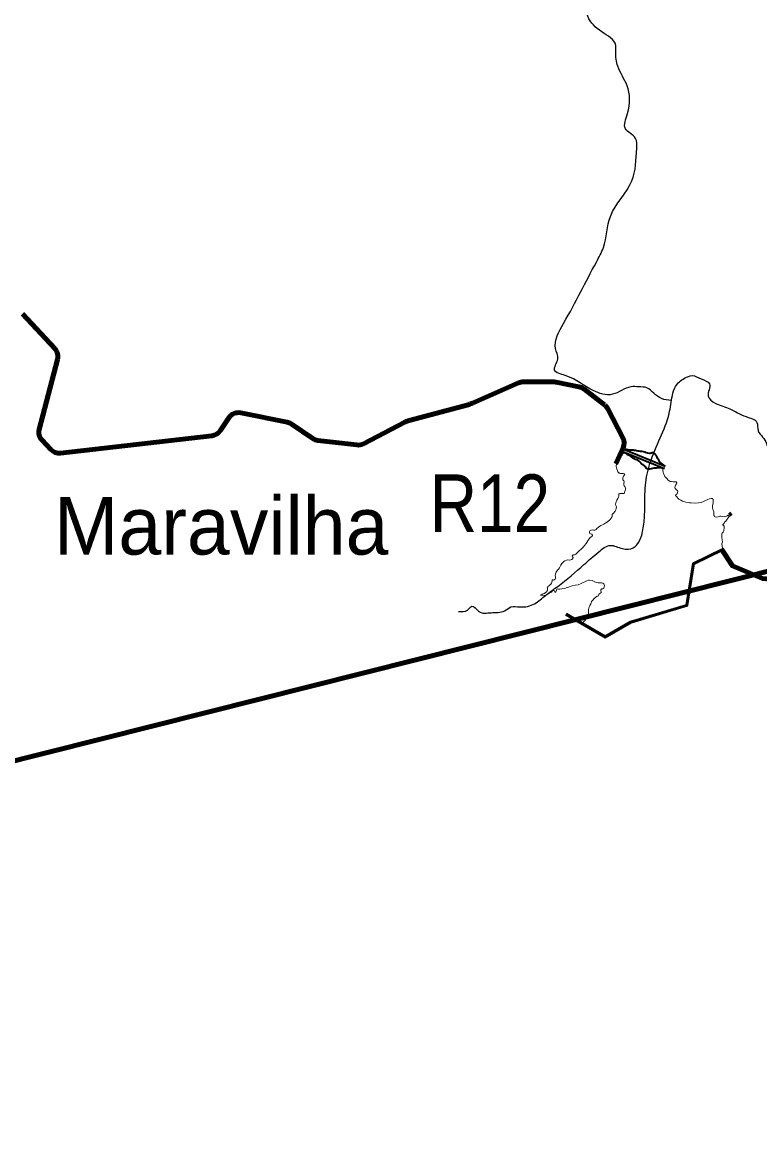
# Model space of a CAD drawing. Extents: x 553962 to 842807, y 8883888 to 9032388.
# Drawn here: x 681628 to 688018, y 8973778 to 8983475 of the extents above; entities that cross this region are included whole.
import ezdxf
from ezdxf.enums import TextEntityAlignment as Align

# ---------------------------------------------------------------- set-up
doc = ezdxf.new("R2010")
doc.units = 0
doc.header["$LTSCALE"] = 200
doc.linetypes.add('LONG_DASH_SHORT_DASH', pattern=[9.9, 6, -1.2, 1.5, -1.2])
for name, color, linetype, lineweight in [('24', 7, 'Continuous', 25), ('7', 7, 'Continuous', 90), ('8', 7, 'Continuous', 13), ('9', 7, 'Continuous', 90)]:
    doc.layers.add(name, color=color, linetype=linetype, lineweight=lineweight)
doc.layers.add('41', color=7, linetype='Continuous')

msp = doc.modelspace()

# ---------------------------------------------------------------- linework, layer by layer
at = {"layer": '24'}
for points in [[(687252.8, 8980199.7), (687166.4, 8980215.3), (687101.2, 8980261.9), (687040.7, 8980308.5), (686970.8, 8980317.8), (686901, 8980317.8), (686742.7, 8980252.6), (686575, 8980285.2), (686332.9, 8980415.6), (686239.8, 8980462.2), (686267.7, 8980560.1), (686249.1, 8980648.6), (686319, 8980867.6), (686603, 8981398.7), (686663.5, 8981524.5), (686724, 8981794.7), (686910.3, 8982102.2), (686952.2, 8982386.4), (686942.9, 8982470.3), (686854.4, 8982554.2), (686873, 8982684.6), (686868.4, 8982926.9), (686789.2, 8983094.6), (686770.6, 8983220.4), (686770.6, 8983276.3), (686649.6, 8983392.8), (686528.5, 8983527.9), (686481.9, 8983644.4), (686337.6, 8983709.6), (686104.8, 8983905.3), (686007, 8984026.5), (685834.7, 8984133.6), (685350.5, 8984748.6), (685266.7, 8984851.1), (685215.5, 8985102.7), (685103.7, 8985419.5), (684959.4, 8985615.2), (684717.3, 8985927.4), (684400.6, 8986216.2), (684191.1, 8986598.3), (684139.9, 8986682.2), (684130.6, 8986994.3), (684088.7, 8987409), (684153.8, 8987749.1), (684107.3, 8988103.2), (684107.3, 8988163.8), (684139.9, 8988163.8), (684139.9, 8988382.8), (684144.5, 8988434), (684116.6, 8988480.6), (684102.6, 8988494.6), (684144.5, 8988555.1), (684177.1, 8988713.5), (684186.5, 8988820.7), (684158.5, 8988895.2), (684144.5, 8989067.6), (684116.6, 8989361.2), (684093.3, 8989528.9), (684051.4, 8989761.8), (683823.3, 8990125.3), (683259.9, 8990786.8)], [(685407.2, 8978371.7), (685484.9, 8978382.8), (685523.7, 8978416.1), (685584.8, 8978371.7), (685690.2, 8978360.6), (685806.8, 8978377.2), (685862.3, 8978410.5), (685940.1, 8978410.5), (686067.7, 8978438.3), (686162.1, 8978510.4), (686267.6, 8978588.1), (686495.2, 8978776.9), (686622.8, 8978887.9), (686722.7, 8978943.4), (686828.2, 8978915.7), (686922.6, 8978921.2), (686978.1, 8978987.8), (687011.4, 8979109.9), (687022.5, 8979248.7), (687028, 8979465.2), (687066.9, 8979653.9), (687155.7, 8979876), (687233.4, 8980086.9), (687261.2, 8980242.3), (687288.9, 8980320.1), (687366.7, 8980392.2), (687433.3, 8980414.4), (687511, 8980386.7), (687583.1, 8980342.2), (687572, 8980236.8), (687633.1, 8980175.7), (687760.8, 8980125.8), (687899.6, 8980059.2), (687993.9, 8980009.2), (688005, 8979937), (688043.9, 8979881.5), (688077.2, 8979826), (688110.5, 8979765), (688166, 8979776.1), (688243.7, 8979820.5), (688343.6, 8979848.2), (688376.9, 8979776.1), (688432.4, 8979737.2), (688532.4, 8979737.2), (688554.6, 8979826), (688599, 8979820.5), (688632.3, 8979742.8), (688754.4, 8979731.7), (688920.9, 8979687.2), (689020.8, 8979620.6), (689009.7, 8979548.5), (688982, 8979481.8), (689059.7, 8979443), (689109.7, 8979370.8), (689176.3, 8979304.2)]]:
    msp.add_spline(points, degree=3, dxfattribs=at)
at = {"layer": '7'}
for p, q in [((681628.1, 8980950.8), (681909.1, 8980648.2)), ((681932.5, 8980554.8), (681773.8, 8979948.7)), ((685528.5, 8980176.1), (685929.1, 8980352.1)), ((685969.3, 8980360.5), (686215.7, 8980360.5)), ((686255.4, 8980356.7), (686451.4, 8980318.6)), ((686493.2, 8980299.8), (686674.6, 8980160.8)), ((683520.5, 8980092.1), (683921.7, 8980011.8)), ((684980.5, 8980026.1), (685490.8, 8980162.8)), ((686702.7, 8980127.2), (686832.6, 8979874.9)), ((683342.1, 8979936.7), (683417.8, 8980049.7)), ((683958.5, 8979996.3), (684144.9, 8979869.1)), ((684583.1, 8979824.5), (684943.4, 8980011.7)), ((681798.2, 8979854.2), (681875.3, 8979773.6)), ((681958.9, 8979743.4), (683270.4, 8979893.1)), ((684189.9, 8979852.3), (684525.6, 8979813.9)), ((686835, 8979788.3), (686772.7, 8979648.9))]:
    msp.add_line(p, q, dxfattribs=at)
msp.add_lwpolyline([(687687.2, 8978910.9), (687782.4, 8978765.4), (688043, 8978657), (688322.2, 8978630), (688619.4, 8978751.8), (688820.4, 8978910.6), (689404, 8978966.5)], dxfattribs=at)
for centre, radius, start, end in [((681835.8, 8980580.1), 100, 345.32582, 42.88041), ((685969.3, 8980260.5), 100, 90, 113.71924), ((686215.7, 8980152.7), 207.8, 79.00606, 90), ((686432.3, 8980220.5), 100, 52.53579, 79.00606), ((683500.9, 8979994), 100, 78.68464, 146.17278), ((685423, 8980416.1), 262.2, 284.99441, 293.71924), ((686613.8, 8980081.4), 100, 27.25813, 52.53579), ((683902.1, 8979913.7), 100, 55.67907, 78.68464), ((685027.8, 8979849.3), 183.1, 104.99441, 117.46255), ((681870.5, 8979923.3), 100, 165.32582, 223.70762), ((683259, 8979992.4), 100, 276.51151, 326.17278), ((684201.3, 8979951.7), 100, 235.67907, 263.46608), ((684537, 8979913.2), 100, 263.46608, 297.46255), ((686743.7, 8979829.1), 100, 335.90291, 27.25813), ((681947.6, 8979842.7), 100, 223.70762, 276.51151)]:
    msp.add_arc(centre, radius, start, end, dxfattribs=at)
at = {"layer": '7', "linetype": 'LONG_DASH_SHORT_DASH', "lineweight": 60}
msp.add_spline([(683598.6, 8994777.1), (684397.7, 8994464.4), (685057.9, 8994117), (685335.8, 8993804.3), (685509.6, 8993491.6), (685648.5, 8993005.2), (685787.5, 8992692.5), (686065.5, 8992275.5), (686343.4, 8991858.6), (686725.6, 8991615.4), (687073, 8991302.7), (687420.5, 8990920.5), (687906.9, 8989912.9), (688323.8, 8989079.1), (688636.5, 8988384.2), (688984, 8987863), (689435.6, 8987654.6), (689817.8, 8987515.6), (690269.5, 8987168.1), (690582.2, 8986959.7), (690825.4, 8986994.4), (691033.9, 8986716.5), (691311.8, 8986369), (691902.5, 8985500.4), (692354.1, 8985153), (692666.8, 8984701.3), (692875.3, 8984214.9), (693158.7, 8983934.4), (693502.3, 8983815), (693545.2, 8983676.6), (693602.5, 8983504.7), (693621.6, 8983017.8), (693570.2, 8982929.4), (693397.3, 8982487.9), (693500.7, 8982373.5), (693769.5, 8982043.9), (693907.8, 8981934.1), (694056.6, 8981574.3), (694126.1, 8980775.2), (694195.6, 8980288.8), (694332.5, 8979985.6), (694542.5, 8979770.8), (694432.7, 8979351), (694365.9, 8979193.5), (694122.6, 8978945.4), (693898.3, 8978539.8), (694012.8, 8978253.5), (694475.7, 8978549.3), (695243.9, 8979169.6), (695396.6, 8979322.3), (696002.5, 8979718.4), (696732.6, 8980376.8), (697123.8, 8980615.4), (697739.5, 8980636.2), (698156.4, 8980636.2)], degree=3, dxfattribs=at)
at = {"layer": '8', "lineweight": 35}
for p, q in [((686824.4, 8979760.3), (687192.8, 8979611.1)), ((686831.9, 8979778.8), (687200.3, 8979629.6))]:
    msp.add_line(p, q, dxfattribs=at)
at = {"layer": '8'}
msp.add_line((686843.2, 8979752.7), (687179.2, 8979616.6), dxfattribs=at)
at = {"layer": '8', "lineweight": 53}
msp.add_line((687753.4, 8979224.4), (687774.2, 8979202.4), dxfattribs=at)
at = {"layer": '8'}
for points in [[(686823.3, 8979393.6), (686834.8, 8979392.8), (686842.6, 8979394.3), (686846, 8979399.1), (686847.5, 8979405.4), (686849.7, 8979411.7), (686853, 8979420.5), (686856, 8979431.3), (686856, 8979440.5), (686853.4, 8979446.8), (686848.2, 8979453.1), (686843.4, 8979460.5), (686839.7, 8979467.9), (686839.7, 8979475), (686841.6, 8979482.2), (686842.7, 8979490), (686842.3, 8979497), (686840.8, 8979501.8), (686837.8, 8979506.3), (686833, 8979512.6), (686831.9, 8979515.5), (686832.3, 8979520), (686833, 8979527.7), (686836, 8979537.4), (686837.8, 8979544), (686843.8, 8979550.3), (686847.5, 8979555.1), (686848.6, 8979558.8), (686847.5, 8979561.8), (686843, 8979564.4), (686837.8, 8979566.2), (686827.8, 8979566.6), (686820.4, 8979566.6), (686813, 8979567.7), (686806.3, 8979568.5), (686800, 8979570.3), (686793.4, 8979574.4), (686789.6, 8979580.5), (686786.3, 8979588.3), (686783, 8979598.3), (686779.6, 8979606.8), (686776.3, 8979616.8), (686774.4, 8979625.7), (686775.5, 8979636.1), (686777.4, 8979645), (686780, 8979653.5), (686784.4, 8979661.2), (686791.1, 8979670.1), (686796.3, 8979681.2), (686803.3, 8979690.5), (686808.3, 8979699.3), (686814.2, 8979708.9), (686819.8, 8979719.3), (686827.2, 8979726.3), (686832, 8979735.9), (686842.7, 8979751.5), (686843.2, 8979752.7)], [(687179.2, 8979616.6), (687178.8, 8979615.4), (687177.8, 8979604.3), (687177.8, 8979593.1), (687181.3, 8979578.4), (687185, 8979567.8), (687190, 8979553.7), (687197.1, 8979540), (687206.3, 8979529.4), (687215.4, 8979519.2), (687222.5, 8979512.1), (687233.1, 8979504), (687242.8, 8979498.5), (687253.9, 8979495.9), (687269.1, 8979494.4), (687281.8, 8979493.4), (687287.4, 8979492.9), (687293, 8979492.9), (687297.5, 8979491.4), (687298.5, 8979488.8), (687299.1, 8979484.8), (687296, 8979478.2), (687289.4, 8979466.6), (687286.4, 8979459.8), (687284.3, 8979452.8), (687283.3, 8979447.7), (687283.3, 8979441.1), (687285.4, 8979436.6), (687292.5, 8979430), (687298.6, 8979424.4), (687304.6, 8979417.8), (687308.7, 8979410.7), (687307.2, 8979403.6), (687305.1, 8979397.1), (687302.6, 8979391), (687297.5, 8979386.9), (687290.9, 8979381.8), (687289.4, 8979376.8), (687290.9, 8979372.7), (687292.5, 8979369.7), (687297, 8979366.2), (687303.4, 8979361)], [(686169.2, 8978540.6), (686177, 8978550.7), (686180.1, 8978559.9), (686179.7, 8978567.3), (686178.4, 8978573.7), (686177.7, 8978579.1), (686181.4, 8978583.5), (686186.5, 8978588.3), (686190.2, 8978592), (686206.8, 8978606.9), (686213.2, 8978616), (686218, 8978624.4), (686218.7, 8978632.5), (686218.7, 8978641), (686221, 8978643.7), (686223.4, 8978645), (686224.8, 8978645.4), (686226.1, 8978644.7), (686233.6, 8978642.7), (686238.3, 8978645), (686244.4, 8978651.1), (686248.5, 8978658.6), (686248.8, 8978665.7), (686247.4, 8978670.7), (686244.7, 8978681.2), (686247.1, 8978695.8), (686254.9, 8978712.3), (686264.4, 8978727.9), (686275.7, 8978738.3), (686284.1, 8978749.8), (686287.2, 8978756.2), (686290.9, 8978767.8), (686294.3, 8978773.5), (686302.4, 8978785.3), (686320.3, 8978805.3), (686329.8, 8978810.7), (686342.7, 8978816.1), (686351.2, 8978817.8), (686367.4, 8978816.1), (686382, 8978817.1), (686390.8, 8978821.5), (686398.9, 8978830), (686400.2, 8978839.1), (686395.8, 8978844.2), (686392.1, 8978851.3), (686393.5, 8978854.3), (686397.9, 8978858.7), (686403, 8978860.4), (686412.1, 8978862.1), (686423.4, 8978866.4), (686431.2, 8978872.8), (686440.3, 8978881.6), (686454.6, 8978897.2), (686474.2, 8978913.4), (686490.4, 8978930.7), (686500.2, 8978943.8), (686513.8, 8978960.4), (686533.5, 8978990.5), (686549.8, 8979011.1), (686563, 8979021.9), (686568.4, 8979029.4), (686568.7, 8979033.4), (686567.4, 8979037.2), (686563.3, 8979040.2), (686551.1, 8979043.2), (686546.1, 8979046.6), (686543, 8979054.1), (686543.7, 8979062.8), (686547.1, 8979068.9), (686551.8, 8979073), (686557.9, 8979076), (686566, 8979077.1), (686579.2, 8979075.7), (686589.7, 8979076.4), (686601.2, 8979082.5), (686608, 8979089.6), (686620.9, 8979102.4), (686633.1, 8979110.5), (686641.1, 8979114.6), (686654.6, 8979120.3), (686667.5, 8979128.1), (686684.4, 8979137.6), (686700.6, 8979148), (686720.9, 8979168.7), (686729.7, 8979179.1), (686738.9, 8979193.7), (686739.2, 8979198.4), (686739.2, 8979206.5), (686740.2, 8979209.9), (686744.3, 8979217), (686750.4, 8979222.1), (686765.3, 8979241.3), (686771.7, 8979250.8), (686775.5, 8979262.3), (686776.8, 8979278.2), (686772.1, 8979290.3), (686769, 8979301.5), (686770, 8979312), (686780.2, 8979334), (686790, 8979349.5), (686794.1, 8979363.4)], [(686795.2, 8979363.5), (686796.3, 8979369.6), (686797.4, 8979374.7), (686797, 8979379.9), (686797, 8979384.7), (686797.8, 8979388.1), (686801.5, 8979391.1), (686807.1, 8979392.2), (686815.9, 8979392.9), (686823.3, 8979393.6)], [(687302.4, 8979362.7), (687305.1, 8979357), (687317, 8979345), (687334, 8979335.8), (687350.6, 8979326.9), (687377.6, 8979318), (687396.9, 8979316.1), (687410.6, 8979313), (687424.9, 8979311.5), (687460.4, 8979310.3), (687487, 8979311.1), (687511.7, 8979316.5), (687529.8, 8979324.6), (687549.5, 8979333.1), (687569.2, 8979340.4), (687583.1, 8979347.3), (687596.6, 8979351.2), (687607, 8979350.4), (687610.5, 8979347.7), (687613.6, 8979343.5), (687614.7, 8979336.5), (687615.2, 8979324.4), (687615.2, 8979312.1), (687609.8, 8979286.6), (687609, 8979268.9), (687612.1, 8979258.5), (687620.2, 8979233.4), (687621, 8979222.3), (687621, 8979206.5), (687622.6, 8979201.8), (687626.4, 8979195.3), (687632.6, 8979190.7), (687643, 8979189.1), (687657.7, 8979190.7), (687666.2, 8979194.1), (687673.9, 8979196.1), (687680.7, 8979195.6), (687693.4, 8979194.5), (687710, 8979191), (687724.3, 8979192.9), (687735.5, 8979199.5), (687743.4, 8979205.9)], [(687754.7, 8979193.2), (687750.7, 8979190), (687744.9, 8979181.6), (687737.2, 8979170.4), (687724.8, 8979153.4), (687714, 8979144.2), (687709.4, 8979135.3), (687703.6, 8979129.5), (687700.1, 8979125.3), (687700.1, 8979122.2), (687700.5, 8979119.5), (687705.1, 8979114.9), (687709.4, 8979109.5), (687710.9, 8979101), (687709, 8979091), (687708.2, 8979077.1), (687707.1, 8979069), (687702.8, 8979057.9), (687694.3, 8979048.6), (687690.5, 8979042.4), (687689, 8979030.5), (687689.3, 8979010.1), (687694.3, 8978991.2), (687694.7, 8978973.5), (687691.3, 8978956.5), (687694.8, 8978920.5), (687695.7, 8978915.1)], [(687743.4, 8979205.9), (687755.2, 8979193.5), (687754.7, 8979193.2)], [(687695.7, 8978915.1), (687442.2, 8978790.7), (687384.9, 8978429.5), (686899.1, 8978285.4), (686679.7, 8978155.7), (686484.6, 8978269.6)], [(686484.6, 8978269.6), (686485.7, 8978274.1), (686488.4, 8978278.8), (686493.5, 8978284.6), (686498.9, 8978289), (686507.1, 8978297.1), (686521.3, 8978315.7), (686525.4, 8978322.5), (686529.8, 8978327.2), (686534.5, 8978340.4), (686535.9, 8978351.9), (686535.2, 8978389.1), (686539.6, 8978411), (686544.7, 8978423.6), (686554.5, 8978437.8), (686556.9, 8978444.2), (686559.2, 8978454.3), (686561.4, 8978458.4), (686565.8, 8978463.8), (686575.2, 8978470.9), (686580.7, 8978479.3), (686586.4, 8978485.8), (686596.9, 8978494.5), (686608.4, 8978502.3), (686619.9, 8978506.7), (686622.3, 8978509.4), (686624, 8978513.8), (686624.7, 8978519.9), (686628.4, 8978523.3), (686633.1, 8978525.3), (686641.9, 8978531.1), (686645, 8978535.8), (686645.3, 8978539.8), (686641.6, 8978549.7), (686640.9, 8978556.1), (686642.6, 8978559.3), (686647, 8978563.3), (686649.1, 8978566.1), (686657.5, 8978567.4), (686666, 8978571.1), (686668.7, 8978575.9), (686671.7, 8978585.7), (686672.1, 8978595.8), (686669.4, 8978605.3), (686666.3, 8978610.7), (686657.9, 8978617.5), (686647, 8978618.8), (686634.8, 8978618.5), (686618.3, 8978618.8), (686605.7, 8978621.8), (686594.2, 8978626.2), (686567.2, 8978638.5), (686543.9, 8978643.5), (686533.1, 8978641.5), (686518.8, 8978635.1), (686471.1, 8978612.1), (686444, 8978600.9), (686419.7, 8978599.6), (686392.2, 8978592.8), (686360.8, 8978580.6), (686349, 8978579.5), (686327.6, 8978571.4), (686303.6, 8978566.6), (686284.7, 8978562.9), (686275.5, 8978565.3), (686265, 8978566.3), (686258.9, 8978562.9), (686256.2, 8978556.8), (686251.8, 8978540.3), (686247.8, 8978537.9), (686245, 8978537.9), (686242.3, 8978540.9), (686238.6, 8978550.1), (686235.2, 8978551.8), (686229.8, 8978551.8), (686221.7, 8978549.7), (686212.9, 8978538.6), (686205.1, 8978535.9), (686194.9, 8978529.1), (686180.7, 8978522.3), (686164.1, 8978508.8), (686158.7, 8978508.8), (686152.3, 8978510.2), (686143.8, 8978513.2), (686131, 8978512.9), (686120.8, 8978509.2), (686122.8, 8978514.2), (686126.6, 8978518.3), (686131.6, 8978521.3), (686140.1, 8978525), (686153.3, 8978528.1), (686160.1, 8978533.5), (686169.2, 8978540.6)]]:
    msp.add_lwpolyline(points, dxfattribs=at)
at = {"layer": '8', "lineweight": 35}
for points in [[(686334.6, 8978345.6), (686679.7, 8978144.1), (686903.1, 8978276.1), (687393.8, 8978421.7), (687451.3, 8978784), (687699.6, 8978905.9)], [(686339.6, 8978354.2), (686679.7, 8978155.7), (686899.1, 8978285.4), (687384.9, 8978429.5), (687442.2, 8978790.7), (687695.7, 8978915.1)]]:
    msp.add_lwpolyline(points, dxfattribs=at)
for points in [[(687192.8, 8979611.1), (687171.7, 8979612.8), (687152.1, 8979616.2), (687133, 8979614.5), (687110, 8979613.3), (687089.3, 8979610.5), (687067.4, 8979604.9), (687054.5, 8979604.9), (687042.8, 8979606.1), (687037.7, 8979610.5), (687022.6, 8979630.2), (686995.1, 8979650.9), (686974.3, 8979672.8), (686932.3, 8979693), (686906, 8979709.3), (686888, 8979721.6), (686871.8, 8979729.5), (686860, 8979738.4), (686846, 8979745.7), (686824.4, 8979760.3)], [(686831.9, 8979778.8), (686844.8, 8979778.3), (686860, 8979776), (686875.1, 8979774.3), (686892.5, 8979771.5), (686908.8, 8979772.1), (686931.7, 8979769.3), (686971, 8979762.6), (687021.5, 8979754.1), (687071.3, 8979742.9), (687080.9, 8979746.3), (687091.5, 8979747.4), (687107.2, 8979739.6), (687112.3, 8979730.6), (687121.8, 8979718.8), (687131.9, 8979699.2), (687145.3, 8979679), (687156, 8979662.7), (687167.8, 8979653.7), (687179.6, 8979644.2), (687200.3, 8979629.6)]]:
    msp.add_spline(points, degree=3, dxfattribs=at)
at = {"layer": '9'}
msp.add_lwpolyline([(658746.8, 8975176), (664691.5, 8973777.5), (669474.2, 8974039.3), (694202.6, 8980257.8)], dxfattribs=at)

# ---------------------------------------------------------------- texts
at = {"layer": '41'}
msp.add_text('Maravilha', height=500, dxfattribs=at).set_placement((681902.6, 8978864.1))
at = {"layer": '9', "width": 0.85}
msp.add_text('R12', height=500, dxfattribs=at).set_placement((685680.1, 8979058.5), align=Align.CENTER)

doc.saveas('drawing.dxf')
